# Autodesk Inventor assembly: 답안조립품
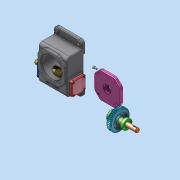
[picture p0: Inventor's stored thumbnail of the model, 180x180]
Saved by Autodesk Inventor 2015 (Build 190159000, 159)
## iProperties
Created: 2026-02
Part Number: 답안조립품
Document SubType Name: Assembly
Designer: Administrator
Author: Administrator
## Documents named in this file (14)
- C:\Users\Administrator\Desktop\760203V1004\답안조립품.iam
- C:\Users\Administrator\Desktop\760203V1004\본체.ipt
- C:\Users\Administrator\Desktop\760203V1004\6각 구멍붙이 볼트 M4x10.ipt
- C:\Users\Administrator\Desktop\760203V1004\6각 구멍붙이 볼트 M5x10.ipt
- C:\Users\Administrator\Desktop\760203V1004\뒷커버.ipt
- C:\Users\Administrator\Desktop\760203V1004\앞커버.ipt
- C:\Users\Administrator\Desktop\760203V1004\오일 실 17 32 8.ipt
- C:\Users\Administrator\Desktop\760203V1004\웜 샤프트.ipt
- C:\Users\Administrator\Desktop\760203V1004\웜 휠 커버.ipt
- C:\Users\Administrator\Desktop\760203V1004\웜 휠.ipt
- C:\Users\Administrator\Desktop\760203V1004\축.ipt
- C:\Users\Administrator\Desktop\760203V1004\칼라.ipt
- C:\Users\Administrator\Desktop\760203V1004\테이퍼 롤러 베어링 30203.ipt
- C:\Users\Administrator\Desktop\760203V1004\평행 키 5x5x16.ipt
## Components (9 placed, 2 different names)
1. 6각 구멍붙이 볼트 M4x10:1
2. 6각 구멍붙이 볼트 M5x10:1
3. 6각 구멍붙이 볼트 M4x10:2
4. 6각 구멍붙이 볼트 M4x10:3
5. 6각 구멍붙이 볼트 M4x10:4
6. 6각 구멍붙이 볼트 M4x10:5
7. 6각 구멍붙이 볼트 M4x10:6
8. 6각 구멍붙이 볼트 M4x10:7
9. 6각 구멍붙이 볼트 M4x10:8
